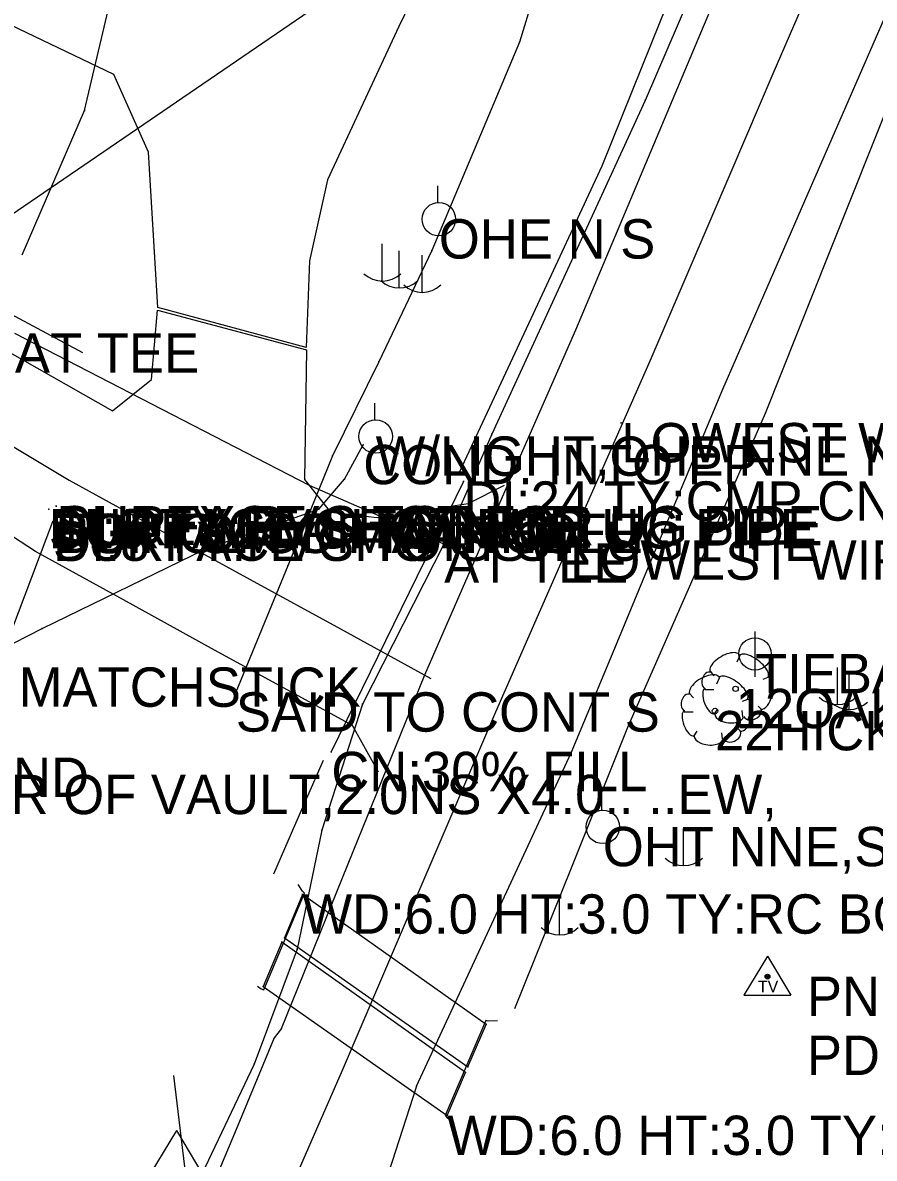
# Model space of a CAD drawing. Extents: x 997398 to 1003416, y 334596 to 337085.
# Drawn here: x 999412.9 to 999521.1, y 336058.3 to 336202.6 of the extents above; entities that cross this region are included whole.
import ezdxf

# ---------------------------------------------------------------- set-up
doc = ezdxf.new("R2010")
doc.units = 0
for name, color, linetype in [('Default', 7, 'Continuous'), ('S_CROSS_DRAIN', 7, 'Continuous'), ('S_CROSS_DRAIN_ANNOT', 7, 'Continuous'), ('S_CURB', 7, 'Continuous'), ('S_DITCHLINE', 7, 'Continuous'), ('S_DRG_PT_SYM', 7, 'Continuous'), ('S_EDGE_CONCRETE', 7, 'Continuous'), ('S_EDGE_PAVEMENT', 7, 'Continuous'), ('S_ELECTRIC_UTILITIES_ANNOT', 7, 'Continuous'), ('S_FIBER_OPTIC_CABLE', 7, 'Continuous'), ('S_FIBER_OPTIC_CABLE_ANNOT', 7, 'Continuous'), ('S_GAS_UTILITIES', 7, 'Continuous'), ('S_GAS_UTILITIES_ANNOT', 7, 'Continuous'), ('S_GRD_PT_SYM', 7, 'Continuous'), ('S_HEADWALL', 7, 'Continuous'), ('S_MANHOLE_ANNOT', 7, 'Continuous'), ('S_MISC_TOPO_POINT', 7, 'Continuous'), ('S_PAVEMENT_CROWN', 7, 'Continuous'), ('S_PRIMARY_CTL', 7, 'Continuous'), ('S_SANITARY_SEWER', 7, 'Continuous'), ('S_SANITARY_SEWER_ANNOT', 7, 'Continuous'), ('S_SECONDARY_CTL', 7, 'Continuous'), ('S_SECONDARY_CTL_ANNOT', 7, 'Continuous'), ('S_SIDE_DRAIN', 7, 'Continuous'), ('S_SIDE_DRAIN_ANNOT', 7, 'Continuous'), ('S_TELEPHONE_UTILITIES_ANNOT', 7, 'Continuous'), ('S_TREE', 7, 'Continuous'), ('S_TREE_ANNOT', 7, 'Continuous'), ('S_UTILITY_POLE', 7, 'Continuous'), ('S_UTILITY_POLE_ANNOT', 7, 'Continuous'), ('S_UTL_PT_SYM', 7, 'Continuous'), ('S_WALL', 7, 'Continuous')]:
    doc.layers.add(name, color=color, linetype=linetype)

msp = doc.modelspace()

# ---------------------------------------------------------------- linework, layer by layer
at = {"layer": 'Default'}
msp.add_line((998964.3, 335872.43), (999557.02, 336277.74), dxfattribs=at)
at = {"layer": 'S_CROSS_DRAIN'}
for p, q in [((999448.43, 336091.83), (999446.14, 336086.31)), ((999471.75, 336075.31), (999448.43, 336091.83)), ((999445.8, 336085.77), (999443.46, 336080.12)), ((999469.13, 336069.2), (999445.8, 336085.77)), ((999446.14, 336086.31), (999469.43, 336069.92)), ((999443.46, 336080.12), (999466.81, 336063.71)), ((999469.43, 336069.92), (999471.75, 336075.31)), ((999466.81, 336063.71), (999469.13, 336069.2))]:
    msp.add_line(p, q, dxfattribs=at)
at = {"layer": 'S_CURB'}
msp.add_lwpolyline([(999444.82, 336073.58), (999439.99, 336061.96), (999435.16, 336050.34)], dxfattribs=at)
at = {"layer": 'S_DITCHLINE'}
for points in [[(999475.43, 336077.33), (999482.6, 336095.21), (999489.77, 336113.08), (999498.51, 336133.02), (999507.25, 336152.96), (999515.39, 336173.39), (999523.54, 336193.82), (999529.15, 336205.87), (999534.77, 336217.93), (999542.66, 336236.46), (999550.55, 336255), (999557.88, 336270.85)], [(999513.68, 336253.86), (999506.39, 336234.78), (999499.1, 336215.7), (999492.79, 336200.03), (999486.47, 336184.36), (999477.43, 336164.94), (999468.38, 336145.52)], [(999420.52, 336160.63), (999406.13, 336168.34), (999391.75, 336176.05)], [(999444.81, 336094.43), (999447.58, 336100.89), (999451.12, 336108.88)]]:
    msp.add_lwpolyline(points, dxfattribs=at)
at = {"layer": 'S_DRG_PT_SYM'}
for points in [[(999468.87, 336144.3), (999468.87, 336144.35), (999468.87, 336144.3), (999468.82, 336144.3), (999468.87, 336144.3), (999468.87, 336144.25), (999468.87, 336144.3), (999468.92, 336144.3)], [(999452.1, 336109.94), (999452.1, 336109.99), (999452.1, 336109.94), (999452.05, 336109.94), (999452.1, 336109.94), (999452.1, 336109.89), (999452.1, 336109.94), (999452.15, 336109.94)], [(999448.43, 336091.83), (999448.43, 336091.88), (999448.43, 336091.83), (999448.38, 336091.83), (999448.43, 336091.83), (999448.43, 336091.78), (999448.43, 336091.83), (999448.48, 336091.83)], [(999445.8, 336085.77), (999445.8, 336085.82), (999445.8, 336085.77), (999445.75, 336085.77), (999445.8, 336085.77), (999445.8, 336085.72), (999445.8, 336085.77), (999445.85, 336085.77)], [(999446.14, 336086.31), (999446.14, 336086.36), (999446.14, 336086.31), (999446.09, 336086.31), (999446.14, 336086.31), (999446.14, 336086.26), (999446.14, 336086.31), (999446.19, 336086.31)], [(999443.46, 336080.12), (999443.46, 336080.17), (999443.46, 336080.12), (999443.41, 336080.12), (999443.46, 336080.12), (999443.46, 336080.07), (999443.46, 336080.12), (999443.51, 336080.12)], [(999471.75, 336075.31), (999471.75, 336075.36), (999471.75, 336075.31), (999471.7, 336075.31), (999471.75, 336075.31), (999471.75, 336075.26), (999471.75, 336075.31), (999471.8, 336075.31)], [(999469.43, 336069.92), (999469.43, 336069.97), (999469.43, 336069.92), (999469.38, 336069.92), (999469.43, 336069.92), (999469.43, 336069.87), (999469.43, 336069.92), (999469.48, 336069.92)], [(999469.13, 336069.2), (999469.13, 336069.25), (999469.13, 336069.2), (999469.08, 336069.2), (999469.13, 336069.2), (999469.13, 336069.15), (999469.13, 336069.2), (999469.18, 336069.2)], [(999466.81, 336063.71), (999466.81, 336063.76), (999466.81, 336063.71), (999466.76, 336063.71), (999466.81, 336063.71), (999466.81, 336063.66), (999466.81, 336063.71), (999466.86, 336063.71)]]:
    msp.add_lwpolyline(points, dxfattribs=at)
at = {"layer": 'S_EDGE_CONCRETE'}
msp.add_lwpolyline([(999522.25, 336257.36), (999519.69, 336264.47), (999515.62, 336268.99), (999499.47, 336276.9), (999496.42, 336275.19), (999489.21, 336260.65), (999482, 336246.12), (999471.33, 336224.11), (999460.67, 336202.1), (999451.61, 336182.6), (999449.32, 336172.31), (999448.89, 336161.32), (999430.05, 336166.38), (999428.87, 336186.15), (999424.48, 336195.98), (999405.32, 336205.16)], dxfattribs=at)
at = {"layer": 'S_EDGE_PAVEMENT'}
for points in [[(999462.94, 336067.47), (999472.76, 336088.65), (999482.57, 336109.83), (999487.39, 336121.37), (999492.2, 336132.92), (999497.02, 336144.47), (999501.83, 336156.01), (999507.04, 336167.97), (999512.25, 336179.93), (999517.46, 336191.88), (999522.67, 336203.84), (999527.6, 336215.54), (999532.53, 336227.24), (999537.46, 336238.93), (999542.4, 336250.63), (999551.59, 336272.84), (999556.87, 336286.38), (999562.16, 336299.92), (999567.44, 336313.47), (999572.72, 336327.01), (999577.33, 336339.09), (999581.94, 336351.18)], [(999445.75, 336074.8), (999454.86, 336097.26), (999463.98, 336119.73), (999473.56, 336141.64), (999483.14, 336163.55), (999488.44, 336176.13), (999493.74, 336188.71), (999499.04, 336201.29), (999504.34, 336213.87), (999513.65, 336236.09), (999522.95, 336258.32), (999528.16, 336270.58), (999533.38, 336282.84), (999538.58, 336295.8), (999543.77, 336308.75), (999548.97, 336321.71), (999554.17, 336334.66), (999558.59, 336346.5)], [(999389.47, 336172.99), (999406.88, 336163.14), (999424.28, 336153.28), (999429.24, 336157.24), (999430.03, 336166.07), (999448.96, 336161.03), (999448.69, 336144.53), (999451.98, 336140.38), (999457.91, 336139.71), (999469.47, 336141.47), (999474.09, 336143.82)], [(999458.08, 336107.37), (999454.78, 336113.28), (999436.87, 336123.07), (999425.69, 336129.23), (999414.5, 336135.38), (999402.39, 336143.26), (999390.28, 336151.14), (999372.85, 336161.33)], [(999445.75, 336074.8), (999444.82, 336073.58)], [(999462.94, 336067.47), (999459.36, 336056.43)]]:
    msp.add_lwpolyline(points, dxfattribs=at)
at = {"layer": 'S_FIBER_OPTIC_CABLE'}
for p, q in [((999481.72, 336218.74), (999476.01, 336200.12)), ((999476.01, 336200.12), (999464.88, 336173.62)), ((999464.88, 336173.62), (999458.12, 336159.51)), ((999458.12, 336159.51), (999452.25, 336147.56)), ((999453.76, 336144.58), (999456.15, 336148.94)), ((999452.25, 336147.56), (999446.58, 336133.58)), ((999450.5, 336140.77), (999453.76, 336144.58)), ((999436.06, 336135.68), (999450.5, 336140.77)), ((999415.36, 336125.59), (999436.06, 336135.68)), ((999446.58, 336133.58), (999439.97, 336117.5)), ((999411.83, 336123.78), (999415.36, 336125.59))]:
    msp.add_line(p, q, dxfattribs=at)
at = {"layer": 'S_GAS_UTILITIES'}
for p, q in [((999420.76, 336191.44), (999427.83, 336221.61)), ((999500.19, 336211.79), (999491.97, 336192.71)), ((999491.97, 336192.71), (999472.47, 336150.32)), ((999412.82, 336173.07), (999420.76, 336191.44)), ((999449.32, 336143.79), (999411.9, 336163.1)), ((999472.47, 336150.32), (999466.43, 336136.42)), ((999466.31, 336136.35), (999449.32, 336143.79)), ((999466.43, 336136.42), (999456.08, 336116.01)), ((999456.08, 336116.01), (999450.88, 336099.99)), ((999450.88, 336099.99), (999447.78, 336084.88)), ((999447.78, 336084.88), (999442.28, 336070.27)), ((999442.28, 336070.27), (999435.67, 336056.26))]:
    msp.add_line(p, q, dxfattribs=at)
at = {"layer": 'S_GRD_PT_SYM'}
for points in [[(999488.93, 336151.72), (999488.93, 336151.77), (999488.93, 336151.72), (999488.88, 336151.72), (999488.93, 336151.72), (999488.93, 336151.67), (999488.93, 336151.72), (999488.98, 336151.72)], [(999416.2, 336140.78), (999416.2, 336140.83), (999416.2, 336140.78), (999416.15, 336140.78), (999416.2, 336140.78), (999416.2, 336140.73), (999416.2, 336140.78), (999416.25, 336140.78)], [(999417.16, 336141.17), (999417.16, 336141.22), (999417.16, 336141.17), (999417.11, 336141.17), (999417.16, 336141.17), (999417.16, 336141.12), (999417.16, 336141.17), (999417.21, 336141.17)], [(999416.74, 336139.2), (999416.74, 336139.25), (999416.74, 336139.2), (999416.69, 336139.2), (999416.74, 336139.2), (999416.74, 336139.15), (999416.74, 336139.2), (999416.79, 336139.2)], [(999482.44, 336136.8), (999482.44, 336136.85), (999482.44, 336136.8), (999482.39, 336136.8), (999482.44, 336136.8), (999482.44, 336136.75), (999482.44, 336136.8), (999482.49, 336136.8)]]:
    msp.add_lwpolyline(points, dxfattribs=at)
at = {"layer": 'S_HEADWALL'}
for points in [[(999442.72, 336080.17), (999443.19, 336079.84), (999443.51, 336079.68), (999448.68, 336091.98), (999448.44, 336092.24), (999447.88, 336093.09)], [(999473.2, 336075.74), (999472.01, 336075.73), (999471.74, 336075.82), (999466.56, 336063.71), (999466.85, 336063.39), (999467.47, 336063.07)]]:
    msp.add_lwpolyline(points, dxfattribs=at)
at = {"layer": 'S_PAVEMENT_CROWN'}
for points in [[(999445.27, 336050.62), (999453.51, 336069.51), (999463.26, 336092.28), (999473, 336115.04), (999482.79, 336137.32), (999492.59, 336159.61), (999497.81, 336171.77), (999503.02, 336183.94), (999508.24, 336196.11), (999513.46, 336208.27), (999522.91, 336231.32), (999532.37, 336254.37), (999537.28, 336266.31), (999542.19, 336278.24), (999547.41, 336291.38), (999552.63, 336304.51), (999557.86, 336317.65), (999563.08, 336330.78), (999567.64, 336342.85)], [(999382.04, 336166.53), (999400.43, 336155.48), (999418.81, 336144.44), (999430.29, 336138.14), (999441.77, 336131.85), (999453.26, 336125.55), (999464.74, 336119.25)]]:
    msp.add_lwpolyline(points, dxfattribs=at)
at = {"layer": 'S_PRIMARY_CTL'}
for q in [(999422.39, 336045.3), (999442.25, 336045.3)]:
    msp.add_line((999432.42, 336061.81), q, dxfattribs=at)
at = {"layer": 'S_SANITARY_SEWER'}
msp.add_line((999358.45, 335985.56), (999416.74, 336139.2), dxfattribs=at)
at = {"layer": 'S_SECONDARY_CTL'}
for p, q in [((999507.51, 336083.99), (999504.5, 336079.03)), ((999507.51, 336083.99), (999510.46, 336079.03)), ((999504.5, 336079.03), (999510.46, 336079.03))]:
    msp.add_line(p, q, dxfattribs=at)
for radius in [0.311, 0.183, 0.103]:
    msp.add_circle((999507.51, 336081.38), radius, dxfattribs=at)
at = {"layer": 'S_SIDE_DRAIN'}
msp.add_line((999468.87, 336144.3), (999452.1, 336109.94), dxfattribs=at)
at = {"layer": 'S_TREE'}
for p, q in [((999504, 336122.19), (999503.62, 336121.34)), ((999500.21, 336120.17), (999500.71, 336119.59)), ((999501.39, 336119.38), (999501.01, 336118.53)), ((999507.57, 336119.4), (999506.91, 336119.13)), ((999499.55, 336117.85), (999500.67, 336117.85)), ((999497.6, 336117.36), (999498.1, 336116.78)), ((999504.96, 336116.59), (999504.3, 336116.32)), ((999496.94, 336115.04), (999498.06, 336115.04)), ((999500.71, 336114.67), (999501.18, 336115.37)), ((999504.39, 336114.4), (999504.31, 336115.18)), ((999506.79, 336115.29), (999506.33, 336115.72)), ((999498.1, 336111.86), (999498.56, 336112.56)), ((999501.78, 336111.59), (999501.7, 336112.37)), ((999504.18, 336112.48), (999503.72, 336112.91))]:
    msp.add_line(p, q, dxfattribs=at)
for centre in [(999503.45, 336117.94), (999500.84, 336115.13)]:
    msp.add_circle(centre, 0.341, dxfattribs=at)
for centre, major_axis, ratio, start_param, end_param in [((999502.11, 336121.15), (1.86, 1.08), 0.471018, 0, 3.141593), ((999505.76, 336120.82), (-1.81, 1.36), 0.405113, 3.141593, 6.283186), ((999499.5, 336118.34), (1.86, 1.08), 0.471018, 0, 3.141593), ((999499.88, 336119.03), (0.31, 1.03), 0.646762, 0, 3.141593), ((999503.15, 336118.01), (-1.81, 1.36), 0.405113, 3.141593, 6.283186), ((999507.12, 336117.41), (0.46, 2.04), 0.482994, 3.141593, 6.283185), ((999500.18, 336116.38), (-0.61, 1.6), 0.420543, 6.283185, 9.424777), ((999497.26, 336116.22), (0.31, 1.03), 0.646762, 0, 3.141593), ((999504.51, 336114.6), (0.46, 2.04), 0.482994, 3.141593, 6.283185), ((999497.57, 336113.57), (-0.61, 1.6), 0.420543, 6.283185, 9.424777), ((999502.64, 336114.6), (-1.83, 0.19), 0.529943, 0, 3.141593), ((999505.6, 336114.89), (1.09, 0.46), 0.711534, 3.141592, 6.283185), ((999500.03, 336111.79), (-1.83, 0.19), 0.529943, 0, 3.141593), ((999502.99, 336112.08), (1.09, 0.46), 0.711534, 3.141592, 6.283185)]:
    msp.add_ellipse(centre, major_axis=major_axis, ratio=ratio, start_param=start_param, end_param=end_param, dxfattribs=at)
at = {"layer": 'S_UTILITY_POLE'}
for p, q in [((999465.64, 336179.75), (999465.64, 336181.86)), ((999458.53, 336174.47), (999458.53, 336169.74)), ((999460.68, 336173.6), (999460.68, 336168.87)), ((999463.59, 336173.03), (999463.59, 336168.3)), ((999457.61, 336152.15), (999457.61, 336154.26)), ((999505.92, 336119.45), (999505.92, 336125.24)), ((999516.35, 336120.67), (999516.35, 336115.94)), ((999517.82, 336120.03), (999517.82, 336115.3)), ((999486.46, 336102.54), (999486.46, 336104.65)), ((999496.81, 336100.19), (999496.81, 336095.46)), ((999481.05, 336091.39), (999481.05, 336086.67))]:
    msp.add_line(p, q, dxfattribs=at)
for centre, radius in [((999465.76, 336177.61), 2.13), ((999457.73, 336150.01), 2.13), ((999505.92, 336122.38), 2.05), ((999486.59, 336100.4), 2.13)]:
    msp.add_circle(centre, radius, dxfattribs=at)
for centre in [(999458.59, 336173.16), (999460.74, 336172.3), (999463.65, 336171.73), (999516.41, 336119.36), (999517.88, 336118.73), (999496.88, 336098.89), (999481.12, 336090.09)]:
    msp.add_arc(centre, 3.41, 226.3972, 313.6028, dxfattribs=at)
at = {"layer": 'S_UTL_PT_SYM'}
for points in [[(999476.01, 336200.12), (999476.01, 336200.17), (999476.01, 336200.12), (999475.96, 336200.12), (999476.01, 336200.12), (999476.01, 336200.07), (999476.01, 336200.12), (999476.06, 336200.12)], [(999491.97, 336192.71), (999491.97, 336192.76), (999491.97, 336192.71), (999491.92, 336192.71), (999491.97, 336192.71), (999491.97, 336192.66), (999491.97, 336192.71), (999492.02, 336192.71)], [(999420.76, 336191.44), (999420.76, 336191.49), (999420.76, 336191.44), (999420.71, 336191.44), (999420.76, 336191.44), (999420.76, 336191.39), (999420.76, 336191.44), (999420.81, 336191.44)], [(999464.88, 336173.62), (999464.88, 336173.67), (999464.88, 336173.62), (999464.83, 336173.62), (999464.88, 336173.62), (999464.88, 336173.57), (999464.88, 336173.62), (999464.93, 336173.62)], [(999458.12, 336159.51), (999458.12, 336159.56), (999458.12, 336159.51), (999458.07, 336159.51), (999458.12, 336159.51), (999458.12, 336159.46), (999458.12, 336159.51), (999458.17, 336159.51)], [(999488.93, 336151.72), (999488.93, 336151.77), (999488.93, 336151.72), (999488.88, 336151.72), (999488.93, 336151.72), (999488.93, 336151.67), (999488.93, 336151.72), (999488.98, 336151.72)], [(999472.47, 336150.32), (999472.47, 336150.37), (999472.47, 336150.32), (999472.42, 336150.32), (999472.47, 336150.32), (999472.47, 336150.27), (999472.47, 336150.32), (999472.52, 336150.32)], [(999456.15, 336148.94), (999456.15, 336148.99), (999456.15, 336148.94), (999456.1, 336148.94), (999456.15, 336148.94), (999456.15, 336148.89), (999456.15, 336148.94), (999456.2, 336148.94)], [(999452.25, 336147.56), (999452.25, 336147.61), (999452.25, 336147.56), (999452.2, 336147.56), (999452.25, 336147.56), (999452.25, 336147.51), (999452.25, 336147.56), (999452.3, 336147.56)], [(999449.32, 336143.79), (999449.32, 336143.84), (999449.32, 336143.79), (999449.27, 336143.79), (999449.32, 336143.79), (999449.32, 336143.74), (999449.32, 336143.79), (999449.37, 336143.79)], [(999453.76, 336144.58), (999453.76, 336144.63), (999453.76, 336144.58), (999453.71, 336144.58), (999453.76, 336144.58), (999453.76, 336144.53), (999453.76, 336144.58), (999453.81, 336144.58)], [(999416.2, 336140.78), (999416.2, 336140.83), (999416.2, 336140.78), (999416.15, 336140.78), (999416.2, 336140.78), (999416.2, 336140.73), (999416.2, 336140.78), (999416.25, 336140.78)], [(999417.16, 336141.17), (999417.16, 336141.22), (999417.16, 336141.17), (999417.11, 336141.17), (999417.16, 336141.17), (999417.16, 336141.12), (999417.16, 336141.17), (999417.21, 336141.17)], [(999450.5, 336140.77), (999450.5, 336140.82), (999450.5, 336140.77), (999450.45, 336140.77), (999450.5, 336140.77), (999450.5, 336140.72), (999450.5, 336140.77), (999450.55, 336140.77)], [(999416.74, 336139.2), (999416.74, 336139.25), (999416.74, 336139.2), (999416.69, 336139.2), (999416.74, 336139.2), (999416.74, 336139.15), (999416.74, 336139.2), (999416.79, 336139.2)], [(999417.03, 336140.19), (999417.03, 336140.24), (999417.03, 336140.19), (999416.98, 336140.19), (999417.03, 336140.19), (999417.03, 336140.14), (999417.03, 336140.19), (999417.08, 336140.19)], [(999417.03, 336140.19), (999417.03, 336140.24), (999417.03, 336140.19), (999416.98, 336140.19), (999417.03, 336140.19), (999417.03, 336140.14), (999417.03, 336140.19), (999417.08, 336140.19)], [(999466.31, 336136.35), (999466.31, 336136.4), (999466.31, 336136.35), (999466.26, 336136.35), (999466.31, 336136.35), (999466.31, 336136.3), (999466.31, 336136.35), (999466.36, 336136.35)], [(999466.43, 336136.42), (999466.43, 336136.47), (999466.43, 336136.42), (999466.38, 336136.42), (999466.43, 336136.42), (999466.43, 336136.37), (999466.43, 336136.42), (999466.48, 336136.42)], [(999482.44, 336136.8), (999482.44, 336136.85), (999482.44, 336136.8), (999482.39, 336136.8), (999482.44, 336136.8), (999482.44, 336136.75), (999482.44, 336136.8), (999482.49, 336136.8)], [(999436.06, 336135.68), (999436.06, 336135.73), (999436.06, 336135.68), (999436.01, 336135.68), (999436.06, 336135.68), (999436.06, 336135.63), (999436.06, 336135.68), (999436.11, 336135.68)], [(999446.58, 336133.58), (999446.58, 336133.63), (999446.58, 336133.58), (999446.53, 336133.58), (999446.58, 336133.58), (999446.58, 336133.53), (999446.58, 336133.58), (999446.63, 336133.58)], [(999415.36, 336125.59), (999415.36, 336125.64), (999415.36, 336125.59), (999415.31, 336125.59), (999415.36, 336125.59), (999415.36, 336125.54), (999415.36, 336125.59), (999415.41, 336125.59)], [(999439.97, 336117.5), (999439.97, 336117.55), (999439.97, 336117.5), (999439.92, 336117.5), (999439.97, 336117.5), (999439.97, 336117.45), (999439.97, 336117.5), (999440.02, 336117.5)], [(999456.08, 336116.01), (999456.08, 336116.06), (999456.08, 336116.01), (999456.03, 336116.01), (999456.08, 336116.01), (999456.08, 336115.96), (999456.08, 336116.01), (999456.13, 336116.01)], [(999450.88, 336099.99), (999450.88, 336100.04), (999450.88, 336099.99), (999450.83, 336099.99), (999450.88, 336099.99), (999450.88, 336099.94), (999450.88, 336099.99), (999450.93, 336099.99)], [(999447.78, 336084.88), (999447.78, 336084.93), (999447.78, 336084.88), (999447.73, 336084.88), (999447.78, 336084.88), (999447.78, 336084.83), (999447.78, 336084.88), (999447.83, 336084.88)], [(999442.28, 336070.27), (999442.28, 336070.32), (999442.28, 336070.27), (999442.23, 336070.27), (999442.28, 336070.27), (999442.28, 336070.22), (999442.28, 336070.27), (999442.33, 336070.27)]]:
    msp.add_lwpolyline(points, dxfattribs=at)
at = {"layer": 'S_WALL'}
msp.add_lwpolyline([(999432.07, 336068.82), (999434.43, 336049.11)], dxfattribs=at)

# ---------------------------------------------------------------- texts
at = {"layer": 'S_CROSS_DRAIN_ANNOT'}
for p in [(999448.43, 336086.83), (999466.81, 336058.71)]:
    msp.add_text('WD:6.0 HT:3.0 TY:RC BOX CN:70% ', height=5, dxfattribs=at).set_placement(p)
at = {"layer": 'S_ELECTRIC_UTILITIES_ANNOT'}
for p in [(999488.93, 336146.72), (999482.44, 336131.8)]:
    msp.add_text('LOWEST WIRE', height=5, dxfattribs=at).set_placement(p)
at = {"layer": 'S_FIBER_OPTIC_CABLE_ANNOT'}
for s, p in [('COND. INTO PP', (999456.15, 336143.94)), ('TOP CL OF MANHOLE', (999417.03, 336135.19)), ('MATCHSTICK', (999412.38, 336115.66)), ('SAID TO CONT S', (999439.97, 336112.5))]:
    msp.add_text(s, height=5, dxfattribs=at).set_placement(p)
at = {"layer": 'S_GAS_UTILITIES_ANNOT'}
for p in [(999411.9, 336158.1), (999466.43, 336131.42)]:
    msp.add_text('AT TEE', height=5, dxfattribs=at).set_placement(p)
at = {"layer": 'S_MANHOLE_ANNOT'}
msp.add_text('BOTTOM OF MANHOLE', height=5, dxfattribs=at).set_placement((999417.03, 336135.19))
at = {"layer": 'S_MISC_TOPO_POINT'}
for p in [(999416.2, 336135.78), (999417.16, 336136.17), (999416.74, 336134.2)]:
    msp.add_text('SURFACE SHOT FOR UG PIPE', height=5, dxfattribs=at).set_placement(p)
at = {"layer": 'S_SANITARY_SEWER_ANNOT'}
for s, p in [('DI:6 TY:PVC TO NW', (999416.2, 336135.78)), ('DI:4 TY:PVC TO NNE', (999417.16, 336136.17)), ('DI:8 TY:PVC TO SSW', (999416.74, 336134.2))]:
    msp.add_text(s, height=5, dxfattribs=at).set_placement(p)
at = {"layer": 'S_SECONDARY_CTL'}
msp.add_text('TV', height=1.5, rotation=360, dxfattribs=at).set_placement((999506.31, 336079.37))
at = {"layer": 'S_SECONDARY_CTL_ANNOT'}
for s, p in [('PN:1107', (999512.51, 336076.38)), ('PD:6" SPIKE', (999512.51, 336068.88))]:
    msp.add_text(s, height=5, dxfattribs=at).set_placement(p)
at = {"layer": 'S_SIDE_DRAIN_ANNOT'}
for s, p in [('DI:24 TY:CMP CN:100% FILL', (999468.87, 336139.3)), ('CN:30% FILL', (999452.1, 336104.94))]:
    msp.add_text(s, height=5, dxfattribs=at).set_placement(p)
at = {"layer": 'S_TELEPHONE_UTILITIES_ANNOT'}
for s, p in [('W END', (999399.03, 336104.21)), ('CTR OF VAULT,2.0NS X4.0.. ..EW,', (999402.44, 336102.02))]:
    msp.add_text(s, height=5, dxfattribs=at).set_placement(p)
at = {"layer": 'S_TREE_ANNOT'}
for s, p in [('12OAK', (999503.45, 336112.94)), ('22HICKORY', (999500.84, 336110.13))]:
    msp.add_text(s, height=5, dxfattribs=at).set_placement(p)
at = {"layer": 'S_UTILITY_POLE_ANNOT'}
for s, p in [('OHE N S', (999465.76, 336172.61)), ('W/LIGHT,OHE NNE NE E W', (999457.73, 336145.01)), ('TIEBACK&TV TO W', (999505.92, 336117.38)), ('OHT NNE,SSW UNDER BRIDGE', (999486.59, 336095.4))]:
    msp.add_text(s, height=5, dxfattribs=at).set_placement(p)

doc.saveas('drawing.dxf')
